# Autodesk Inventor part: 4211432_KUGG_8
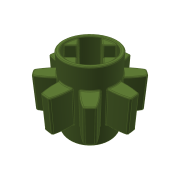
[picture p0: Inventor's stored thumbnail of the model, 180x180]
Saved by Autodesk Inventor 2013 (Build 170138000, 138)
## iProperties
Created: 2013-03
Part Number: 4211432_KUGG_8
Material: Generic
Document SubType Name: Modeling
Designer: perblt
Density: 1 g/cm^3
Translation Standard: STEP AP203
FileName: 4211432_KUGG_8
PreProcessor: PRO/ENGINEER BY PARAMETRIC TECHNOLOGY CORPORATION, 2010370
PostProcessor: Build: 138, Release: 2013 RTM - Date: Thu 03/01/2012
Sent Units: millimeter
Uncertainty: 0.0015758673019310003
Author: perblt
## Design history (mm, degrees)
node "4211432_KUGG_81"
fillet "Fillet1" dims "d0" = 0.1, "d1" = 0.1
node "4211432_KUGG_8"
node "Base1"
